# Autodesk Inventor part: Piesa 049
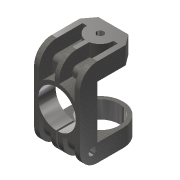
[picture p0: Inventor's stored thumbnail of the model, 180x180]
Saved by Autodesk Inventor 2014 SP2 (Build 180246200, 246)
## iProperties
Created: 2009-01
Part Number: Piesa 049
Document SubType Name: Modeling
Designer: Costel
Material: Steel, Cast
Density: 7.85 g/cm^3
Appearance: Steel - Cast
Author: Costel
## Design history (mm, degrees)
sketch "Sketch2"
  geometry: L1 (-55.4, 0)-(34.2, 0) reference; L2 (0, -10)-(0, 130) reference; L3 (0, 0)-(-49, 0); L4 (-49, 0)-(-49, 100); L5 (-49, 100)-(15, 100); L6 (15, 80)-(15, 100); L7 (15, 80)-(-29, 80); L8 (-29, 80)-(-29, 20); L9 (-29, 20)-(0, 20); L10 (0, 20)-(0, 0)
  constraints: 16 end point, 5 perpendicular, 4 point on line, 2 parallel
  dimensions: "d0" = 49 distance of L3.start L3.end; "d1" = 100 distance of L3.end L4.end; "d2" = 20 distance of L6.start L5.end; "d3" = 20 distance between parallel lines of L3 L9 (= d2); "d4" = 20 distance between parallel lines of L8 L4 (= d2); "d5" = 64 distance between parallel lines of L4 L6
extrude "Extrusion1" new body sketch "Sketch2" stored distance "d6" = 52; taper "d7" = 0 deg
sketch "Sketch3"
  geometry: L1 (52, -29)-(52, 0) reference; L2 (-5.2, 0)-(67.6, 0) reference; L3 (26, -55.4)-(26, 34.2) reference; C1 r 26 at (26, 0)
  constraints: 2 point on line, 1 centre point, 1 tangent
extrude "Extrusion2" join sketch "Sketch3" distance "d8" = 20 (= d2); taper "d9" = 0 deg
chamfer "Chamfer1" distance "d10" = 9; stored, may be unused: second distance "d11" = 12, angle "d12" = 45 deg
chamfer "Chamfer2" distance "d13" = 9; stored, may be unused: second distance "d14" = 12, angle "d15" = 45 deg
fillet "Fillet1" dims "d16" = 20
sketch "Sketch4"
  geometry: L1 (-9, -12)-(-9, -44) reference; L2 (43, -64)-(-9, -64) reference; L3 (-9, -64)-(43, -64) reference; L4 (-14.2, -15)-(58.6, -15) reference; L5 (17, -71.5)-(17, 33.5) reference; L6 (32, -15)-(37, -15); L7 (37, -15)-(37, -64); L8 (2, -15)-(-3, -15); L9 (-3, -15)-(-3, -64); L10 (-3, -64)-(14.5, -64); L11 (19.5, -64)-(37, -64); L12 (19.5, -64)-(19.5, -29.79); L13 (14.5, -64)-(14.5, -29.79); A1 r 15 centre (17, -15) between (2, -15) and (14.5, -29.79); A2 r 15 centre (17, -15) between (19.5, -29.79) and (32, -15)
  constraints: 16 end point, 8 point on line, 4 point on circle, 2 centre point, 2 collinear, 2 parallel, 2 perpendicular, 1 other
  dimensions: "d20" = 6 distance between parallel lines of L1 L9; "d31" = 5 distance between parallel lines of L12 L13
extrude "Extrusion4" cut sketch "Sketch4" distance "d29" = 15; taper "d30" = 0 deg
sketch "Sketch6"
  geometry: L1 (26, -29)-(26, 0) reference; L2 (-26, 0)-(-26, -29) reference; L3 (-26, -49)-(26, -49) reference; L4 (26, -49)-(-26, -49) reference; L5 (0, -56.5)-(0, 48.5) reference; L6 (-7, -49)-(-7, -25.04); L7 (20, -49)-(7, -49); L8 (-7, -49)-(-20, -49); L9 (20, -49)-(20, -16.613); L10 (-20, -49)-(-20, -16.613); L11 (7, -49)-(7, -25.04); A1 r 26 centre (0, 0) between (26, 0) and (-26, 0) reference; A2 r 26 centre (0, 0) between (7, -25.04) and (20, -16.613); A3 r 26.81 centre (0, 0) between (0, 26.81) and (-7, 25.88); A4 r 26 centre (0, 0) between (-20, -16.613) and (-7, -25.04)
  constraints: 13 end point, 7 point on circle, 6 point on line, 4 parallel, 3 centre point, 1 coincident, 1 collinear, 1 concentric, 1 perpendicular, 1 other
  dimensions: "d35" = 26 radius of A2; "d36" = 14 distance between parallel lines of L6 L11; "d37" = 6 distance between parallel lines of L1 L9
extrude "Extrusion5" cut sketch "Sketch6" distance "d44" = 5; taper "d45" = 0 deg
sketch "Sketch7"
  geometry: L1 (-57.2, -20)-(15.6, -20) reference; L2 (-26, -30)-(-26, 110) reference; L3 (-46, 65)-(-46, 46.613); L4 (-6, 65)-(-6, 46.613); L5 (-28.5, 55.88)-(-28.5, 65); L6 (-23.5, 55.88)-(-23.5, 65); L7 (-28.5, 65)-(-46, 65) reference; L8 (-6, 65)-(-23.5, 65) reference; L9 (-46, 65)-(-28.5, 65); L10 (-23.5, 65)-(-6, 65); A1 r 26 centre (-26, 30) between (-6, 46.613) and (-23.5, 55.88); A2 r 26 centre (-26, 30) between (-28.5, 55.88) and (-46, 46.613)
  constraints: 12 end point, 4 parallel, 4 point on circle, 2 centre point, 2 collinear, 1 point on line, 1 other
  dimensions: "d48" = 26 radius of A2; "d49" = 26 radius of A1; "d52" = 50 distance from line of L1 A1.centre
extrude "Extrusion6" cut sketch "Sketch7" distance "d53" = 15; taper "d54" = 0 deg
fillet "Fillet2" dims "d55" = 5
sketch "Sketch8"
  geometry: L1 (52, 0)-(0, 0) reference; L2 (6, -15)-(19, -15) reference; L3 (33, -15)-(46, -15) reference; L4 (6, -15)-(6, 13.387); L5 (19, -15)-(19, 4.96); L6 (33, -15)-(33, 4.96); L7 (46, -15)-(46, 13.387); L8 (6, -15)-(19, -15); L9 (33, -15)-(46, -15); A1 r 26 centre (26, 30) between (46, 46.613) and (28.5, 55.88) reference; A2 r 26 centre (26, 30) between (6, 13.387) and (19, 4.96); A3 r 26 centre (26, 30) between (33, 4.96) and (46, 13.387)
  constraints: 12 end point, 4 point on circle, 3 perpendicular, 2 centre point, 2 parallel, 1 coincident, 1 collinear
  dimensions: "d56" = 26 radius of A2; "d57" = 26 radius of A3
extrude "Extrusion7" cut sketch "Sketch8" distance "d58" = 5; taper "d59" = 0 deg
sketch "Sketch9"
  geometry: L1 (13.387, 0)-(13.387, 5); L2 (33.387, 20)-(28.387, 20); A1 r 20 centre (13.387, 20) between (13.387, 0) and (26.616, 5) reference; A2 r 20 centre (13.387, 20) between (28.387, 6.771) and (33.387, 20) reference; A3 r 15 centre (13.387, 20) between (13.387, 5) and (28.387, 20); A4 r 20 centre (13.387, 20) between (13.387, 0) and (33.387, 20)
  constraints: 4 end point, 4 point on circle, 2 centre point, 2 concentric, 1 coincident
extrude "Extrusion8" cut sketch "Sketch9" distance "d60" = 13; taper "d61" = 0 deg
workplane "Work Plane1"
mirror "Mirror1"
hole "Hole1" diameter "d65" = 8; stored, may be unused: countersink angle "d69" = 90 deg, drill point angle "d71" = 118 deg; dims "d63" = 10, "d64" = 10, "d66" = 6, "d67" = 4, "d68" = 2, "d70" = 8
hole "Hole2" diameter "d74" = 43; stored, may be unused: countersink angle "d78" = 90 deg, drill point angle "d80" = 118 deg; dims "d72" = 10, "d73" = 10, "d75" = 6, "d76" = 4, "d77" = 2, "d79" = 8
sketch "Sketch10"
  geometry: L1 (-20, -29)-(-20, 0) reference; L2 (-80, -29)-(-20, -29) reference; 1 further point
  dimensions: "d81" = 6 distance from line of L2 point (-14, -35); "d82" = 6 distance from line of L1 point (-14, -35)
hole "Hole3" sketch "Sketch10" at (-14, -35) diameter "d83" = 8; stored, may be unused: countersink angle "d87" = 90 deg, drill point angle "d89" = 118 deg; dims "d84" = 6, "d85" = 4, "d86" = 2, "d88" = 8
hole "Hole4" diameter "d92" = 43; stored, may be unused: countersink angle "d96" = 90 deg, drill point angle "d98" = 118 deg; dims "d90" = 10, "d91" = 10, "d93" = 6, "d94" = 4, "d95" = 2, "d97" = 8
sketch "Sketch11"
  geometry: L1 (-27, 33.37)-(-25, 33.37); L2 (-25, 33.37)-(-25, -20); L3 (-25, -20)-(-27, -20); L4 (-27, -20)-(-27, 33.37); L5 (-26, -33.04)-(-26, 110.829) reference; L6 (-4.5, -20)-(-47.5, -20) reference; L7 (-52, -20)-(-46, -20) reference; L8 (0, -20)-(-52, -20) reference; L9 (-6, -20)-(0, -20) reference; L10 (-6, -20)-(-19, -20) reference; L11 (-33, -20)-(-19, -20) reference; L12 (-33, -20)-(-46, -20) reference
  constraints: 8 end point, 2 parallel, 1 collinear, 1 horizontal, 1 perpendicular, 1 other
  dimensions: "d99" = 2 distance between parallel lines of L2 L4
extrude "Extrusion9" cut sketch "Sketch11" distance "d100" = 49; taper "d101" = 0 deg
body "Solid1"
node "Projected Loop1"
node "Projected Loop2"
node "Projected Loop3"
other parameters: "d18" = 15, "d24" = 52, "d25" = 5, "d28" = 5, "d32" = 52 (= d6), "d33" = 6 (= d20), "d34" = 5, "d46" = 52 (= d6), "d47" = 5, "d62" = 0
